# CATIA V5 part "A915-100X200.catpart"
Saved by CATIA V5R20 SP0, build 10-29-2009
Part number: A915-100X200
Source: Unknown
Property "A": "0.000"
Property "ARTICLENO": "A915-100X200"
Property "BOMINFO": "A915-100X200"
Property "CODE": "A915-100X200"
Property "CREATOR": "CADENAS GmbH"
Property "D": "13.500"
Property "D1": "20.000"
Property "FORM": "B"
Property "L": "200.000"
Property "L1": "25.000"
Property "L2": "150.000"
Property "LINA": "A915-100X200"
Property "NB": "A915-100X200"
Property "NBSYN": "$CODE."
Property "NN": "A915"
Property "NT": "VDI 3357 Wear Plates, steel"
Property "SCREW": "M12x25"
Property "SUPPLIER": "CF"
Property "T": "13.000"
Property "W": "100.000"
Bounding box of the stored display mesh (mm): x 0 to 20, y 0 to 200, z -50 to 50
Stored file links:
  C:\Users\borellobunino\Desktop\3D X SITO CF\A915\GSB_OILLESS_G22501100200\CATIAV5\A915-100X200.catpart
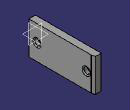
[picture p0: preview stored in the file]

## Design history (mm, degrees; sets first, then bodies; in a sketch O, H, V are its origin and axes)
Body1 "Geometry.1" (main body)
  Solid1 "A915-100X200.catpart": solid without history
